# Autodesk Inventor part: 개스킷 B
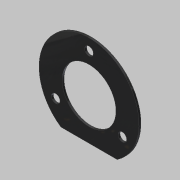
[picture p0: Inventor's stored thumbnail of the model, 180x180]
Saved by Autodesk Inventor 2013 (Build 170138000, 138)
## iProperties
Created: 2020-04
Part Number: 개스킷 B
Material: 고무
Document SubType Name: Modeling
Designer: mduedu
Density: 1 g/cm^3
Author: mduedu
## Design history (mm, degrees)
sketch "스케치1"
  geometry: C1 r 26 at (0, 0); 1 further point
  constraints: 1 centre point, 1 coincident
  dimensions: "d0" = 52 diameter of C1
extrude "돌출1" new body sketch "스케치1" distance "d1" = 1; taper "d2" = 0 deg
sketch "스케치2"
  geometry: L1 (-14.62, -21.5)-(14.62, -21.5); A1 r 26 centre (0, 0) between (-14.62, -21.5) and (14.62, -21.5) reference; 1 further point
  constraints: 2 end point, 2 point on circle, 1 horizontal
  dimensions: "d3" = 21.5 distance from line of L1 point (0, 0)
extrude "돌출2" cut sketch "스케치2" stored distance "d4" = 1; taper "d5" = 0 deg
sketch "스케치3" dims "d6" = 40
  geometry: 3 further points
  constraints: 2 vertical alignment, 1 coincident, 2 other
hole "구멍1" sketch "스케치3" at (0, 20) diameter "d7" = 4.5; stored, may be unused: countersink angle "d11" = 90 deg, drill point angle "d13" = 118 deg; dims "d8" = 6, "d9" = 4, "d10" = 2, "d12" = 8
sketch "스케치4"
  geometry: C1 r 14 at (0, 0); 1 further point
  constraints: 1 centre point, 1 coincident
  dimensions: "d17" = 28 diameter of C1
extrude "돌출3" cut sketch "스케치4" stored distance "d18" = 1; taper "d19" = 0 deg
node "솔리드1"
pattern_circular "원형 패턴1" dims angle "d15" = 360 deg
node "투영된 루프1"
